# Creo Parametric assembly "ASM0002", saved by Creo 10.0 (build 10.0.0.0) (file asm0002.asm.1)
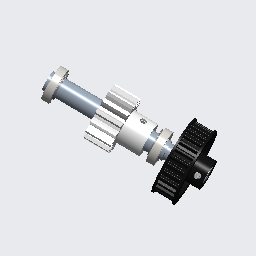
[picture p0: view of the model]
Units: millimeter Newton Second (mmNs); MM, TONNE, SECS

Created from: XX_INLBS_ASM_DESIGN_ABS.ASM

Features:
  1. datum plane "ASM_RIGHT"
  2. datum plane "ASM_TOP"
  3. datum plane "ASM_FRONT"
  4. coordinate system
  5. component "WELLE5FERTIG"
  6. component "ZAHNRAD5"
  7. component "RIEMENRAD"
  8. component "PRT0005"
  9. component "PRT0006"
  10. component "PRT0010.PRT"
  11. component "PRT0012.PRT"
  12. sketch "Skizze 1"
  13. sketch "Skizze 2"
  14. sketch "Skizze 3"
  15. component "61741200.PRT"
  16. component "PRT0001.PRT"

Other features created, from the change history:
  component "PRT0003.PRT"
  component "PRT0014.PRT"
  sketch "Skizze 1"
